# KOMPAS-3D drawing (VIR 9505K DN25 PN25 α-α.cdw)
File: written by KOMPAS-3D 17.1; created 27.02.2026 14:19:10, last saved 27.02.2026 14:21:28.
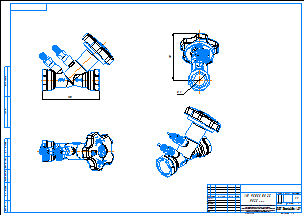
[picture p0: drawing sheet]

Sheet 1: A2, landscape

Title block, sheet 1: name: VIR 9505K DN25 / PN25 р-р; material: Внимание! Данный продукт является объектом авторского права ООО «Торговый Дом АДЛ». / Запрещается изменение, копирование, распространение / (в том числе путем копирования на другие сайты и ресурсы в Интернете) / или любое иное использование информации и объектов без предварительного / согласия правообладателя (ООО «Торговый Дом АДЛ»).; sheets: 1; organisation: ООО "Торговый дом АДЛ"; sheet format: A2

Views: Вид 1, Спереди, Проекционный вид 2, Проекционный вид 3, Вид 4, Изометрия
Referenced files in C:\Users\mipv\Desktop\VIR 9505K STP формат\: VIR 9505K DN25 PN25 р-р.m3d
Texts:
  adm
Dimensions and other numbers on the sheet: 90; 110; 1:1; 1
